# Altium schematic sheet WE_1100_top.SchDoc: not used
size A3; Date: not used; Author: not used; CompanyName: Würth Elektronik eiSos GmbH & Co. KG; Engineer: not used; Organization: not used; Address1: Max-Eyth-Str. 1; Address2: 74638 Waldenburg; Address3: not used; Address4: Germany; DocumentNumber: not used; Revision: not used
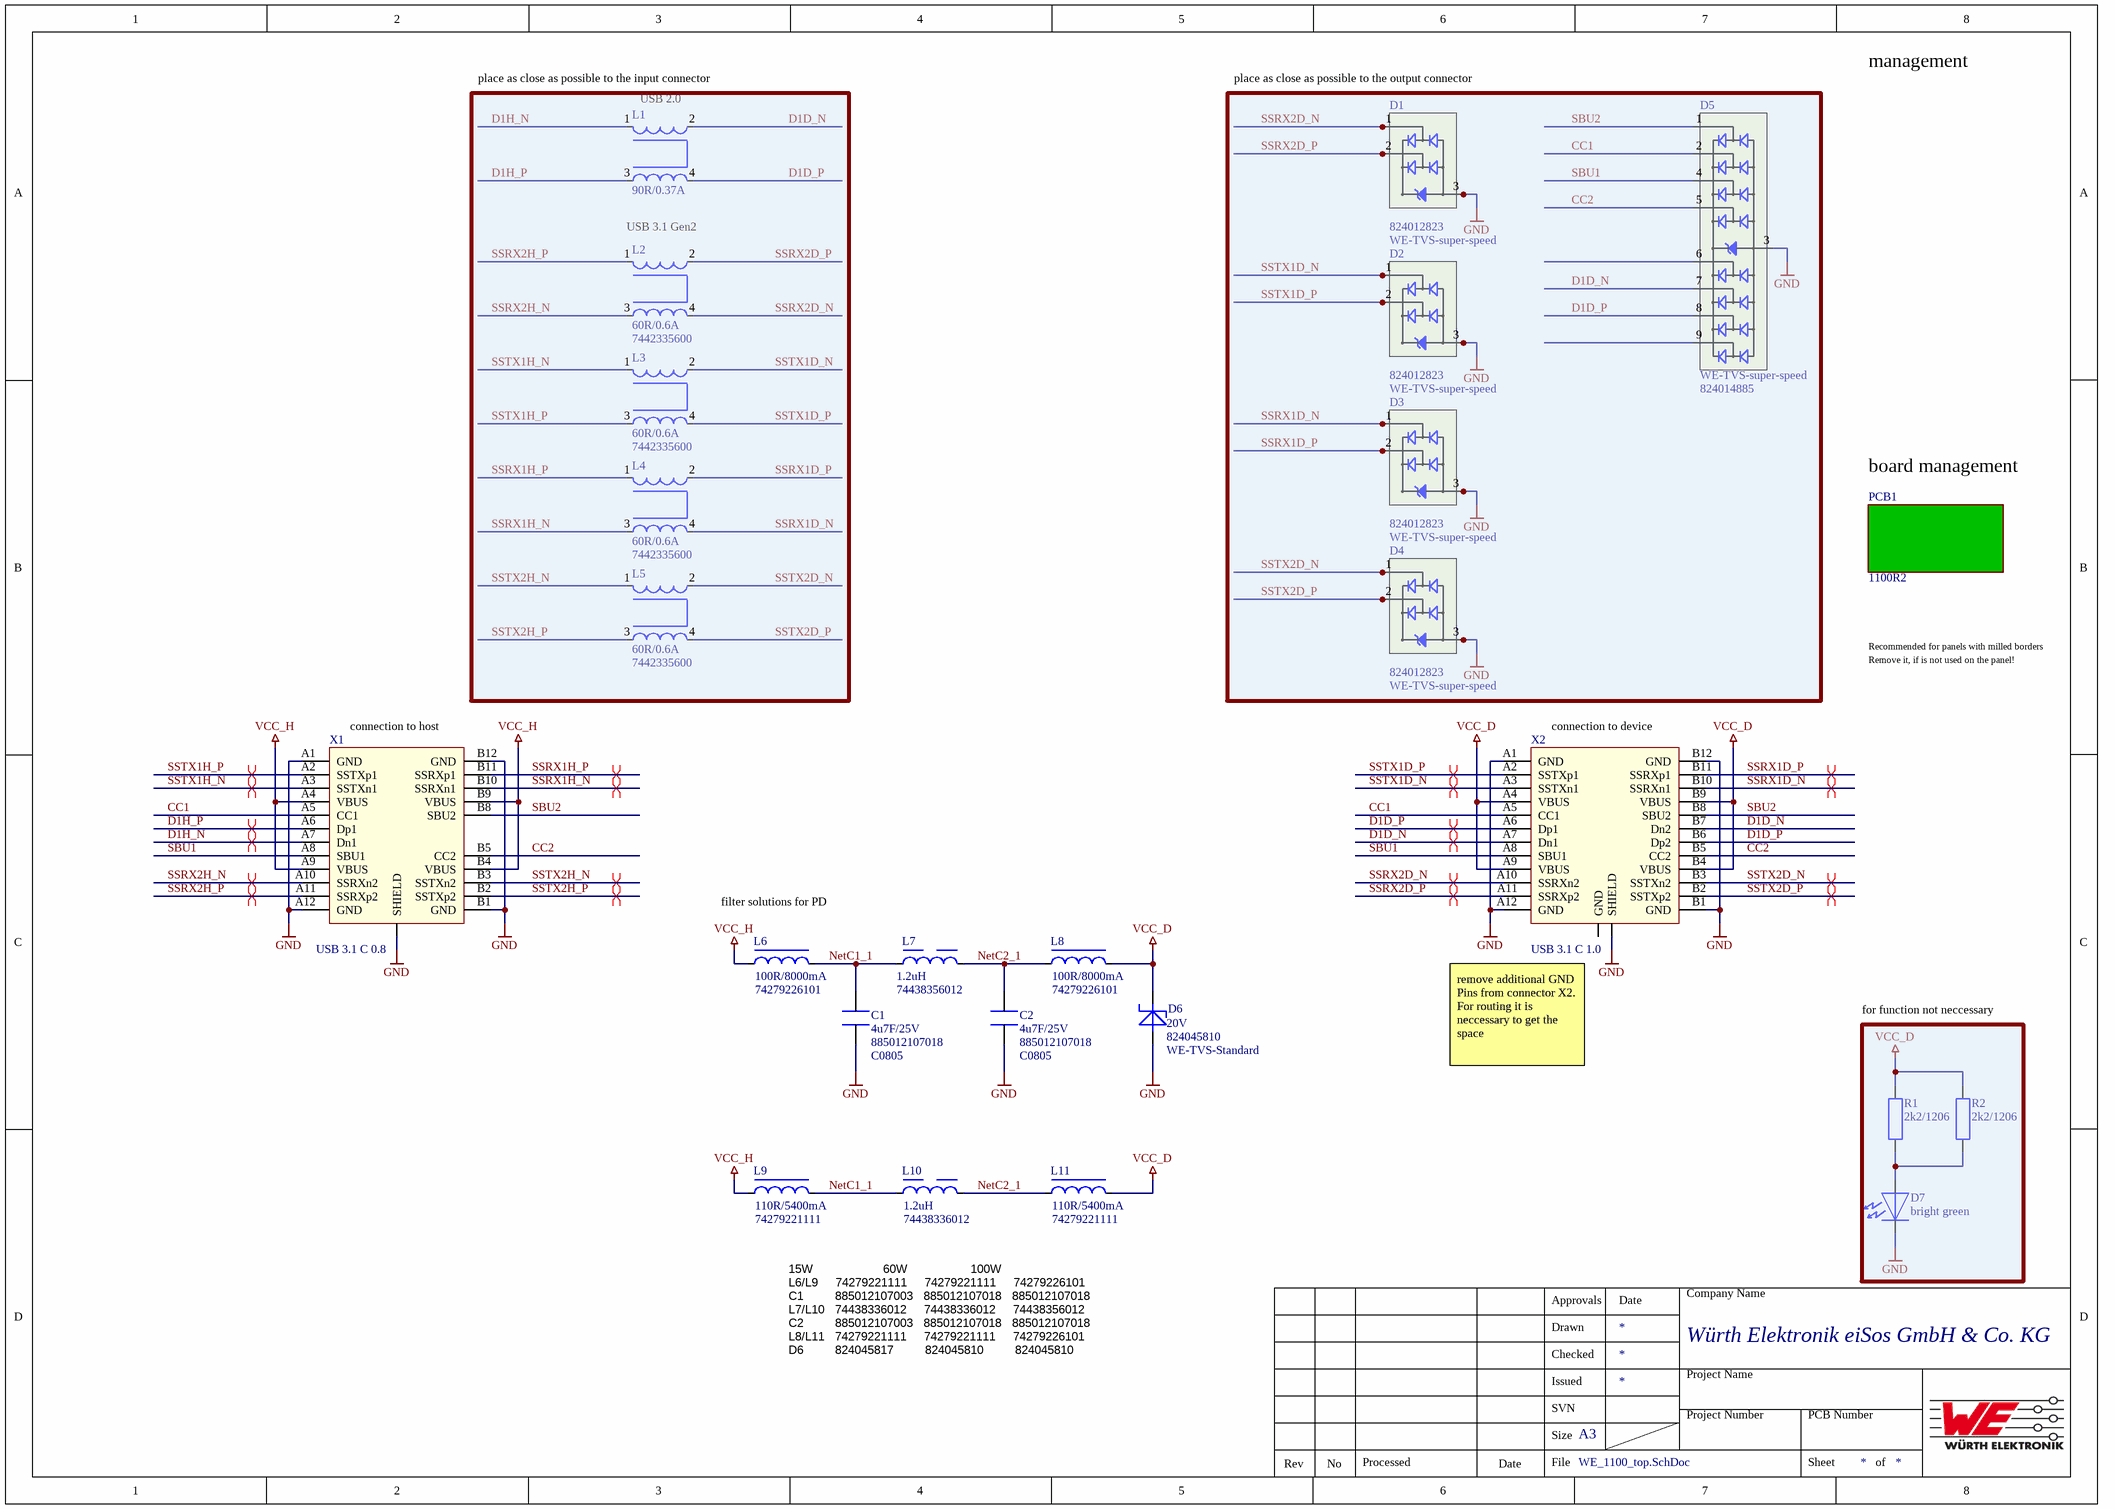
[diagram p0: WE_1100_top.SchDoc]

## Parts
C1  4u7F/25V  Art.-Code: 885012107018  Case: C0805  [C0805 (reflow)]
C2  4u7F/25V  Art.-Code: 885012107018  Case: C0805  [C0805 (reflow)]
D1  WE-TVS-super-speed  Part-No.: 824012823  [DFN88P100X50-6L]
D2  WE-TVS-super-speed  Part-No.: 824012823  [DFN88P100X50-6L]
D3  WE-TVS-super-speed  Part-No.: 824012823  [DFN88P100X50-6L]
D4  WE-TVS-super-speed  Part-No.: 824012823  [DFN88P100X50-6L]
D5  WE-TVS-super-speed  Part-No.: 824014885  [DFN90P380X55-9L]
D6  WE-TVS-Standard  Voltage: 20V  Part-No.: 824045810  [DFN110P160X55-2L]
D7  bright green  [LED-SMD-GR-2014X09L]
L1  90R/0.37A  [WE-CNSW-0805 (REFLOW)]
L2  60R/0.6A  Part-No.: 7442335600  [WE-CNSW-HF-0504 (REFLOW)]
L3  60R/0.6A  Part-No.: 7442335600  [WE-CNSW-HF-0504 (REFLOW)]
L4  60R/0.6A  Part-No.: 7442335600  [WE-CNSW-HF-0504 (REFLOW)]
L5  60R/0.6A  Part-No.: 7442335600  [WE-CNSW-HF-0504 (REFLOW)]
L6  100R/8000mA  Art.-Code: 74279226101  [WE-MPSB_1812]
L7  1.2uH  Art.-Code: 74438356012  [WE-MAPI_4020]
L8  100R/8000mA  Art.-Code: 74279226101  [WE-MPSB_1812]
L9  110R/5400mA  Art.-Code: 74279221111  [WE-MPSB_1206]
L10  1.2uH  Art.-Code: 74438336012  [WE-MAPI_3020]
L11  110R/5400mA  Art.-Code: 74279221111  [WE-MPSB_1206]
PCB1  1100R2  (mechanical)
R1  2k2/1206  [R1206 (reflow)]
R2  2k2/1206  [R1206 (reflow)]
X1  USB 3.1 C 0.8  [632712000011]
X2  USB 3.1 C 1.0  [632723100011]

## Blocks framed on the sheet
place as close as possible to the output connector: D1-D5
for function not neccessary: D7 R1 R2

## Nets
GND: C1.2 C2.2 D1.3(VDD) D1.4(VDD) D2.3(VDD) D2.4(VDD) D3.3(VDD) D3.4(VDD) D4.3(VDD) D4.4(VDD) D5.3(VDD) D6.2(I/O2) D7.1 X1.0(SHIELD) X1.A1(GND) X1.A12(GND) X1.B1(GND) X1.B12(GND) X2.0(SHIELD) X2.A1(GND) X2.A12(GND) X2.B1(GND) X2.B12(GND)
VCC_D: D6.1(I/O1) L8.2 L11.2 R1.2 R2.2 X2.A4(VBUS) X2.A9(VBUS) X2.B4(VBUS) X2.B9(VBUS)
VCC_H: L6.1 L9.1 X1.A4(VBUS) X1.A9(VBUS) X1.B4(VBUS) X1.B9(VBUS)
CC1: D5.2(I/O2) X1.A5(CC1) X2.A5(CC1)
CC2: D5.5(I/O4) X1.B5(CC2) X2.B5(CC2)
D1D_N: D5.7(NC) L1.2 X2.A7(Dn1) X2.B7(Dn2)
D1D_P: D5.8(GND) L1.4 X2.A6(Dp1) X2.B6(Dp2)
D1H_N: L1.1 X1.A7(Dn1)
D1H_P: L1.3 X1.A6(Dp1)
NetC1_1: C1.1 L6.2 L7.1 L9.2 L10.1
NetC2_1: C2.1 L7.2 L8.1 L10.2 L11.1
SBU1: D5.4(I/O3) X1.A8(SBU1) X2.A8(SBU1)
SBU2: D5.1(I/O1) X1.B8(SBU2) X2.B8(SBU2)
SSRX1D_N: D3.1(I/O1) D3.6(I/O1) L4.4 X2.B10(SSRXn1)
SSRX1D_P: D3.2(I/O2) D3.5(I/O2) L4.2 X2.B11(SSRXp1)
SSRX1H_N: L4.3 X1.B10(SSRXn1)
SSRX1H_P: L4.1 X1.B11(SSRXp1)
SSRX2D_N: D1.1(I/O1) D1.6(I/O1) L2.4 X2.A10(SSRXn2)
SSRX2D_P: D1.2(I/O2) D1.5(I/O2) L2.2 X2.A11(SSRXp2)
SSRX2H_N: L2.3 X1.A10(SSRXn2)
SSRX2H_P: L2.1 X1.A11(SSRXp2)
SSTX1D_N: D2.1(I/O1) D2.6(I/O1) L3.2 X2.A3(SSTXn1)
SSTX1D_P: D2.2(I/O2) D2.5(I/O2) L3.4 X2.A2(SSTXp1)
SSTX1H_N: L3.1 X1.A3(SSTXn1)
SSTX1H_P: L3.3 X1.A2(SSTXp1)
SSTX2D_N: D4.1(I/O1) D4.6(I/O1) L5.2 X2.B3(SSTXn2)
SSTX2D_P: D4.2(I/O2) D4.5(I/O2) L5.4 X2.B2(SSTXp2)
SSTX2H_N: L5.1 X1.B3(SSTXn2)
SSTX2H_P: L5.3 X1.B2(SSTXp2)
NetD7_2: D7.2 R1.1 R2.1

Not connected (* = marked no-connect by the designer): D5 6(NC) 9(NC); X2 GND

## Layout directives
differential pair: D1D_N, D1D_P, D1H_N, D1H_P, SSRX1D_N, SSRX1D_P, SSRX1H_N, SSRX1H_P, SSRX2D_N, SSRX2D_P, SSRX2H_N, SSRX2H_P, SSTX1D_N, SSTX1D_P, SSTX1H_N, SSTX1H_P, SSTX2D_N, SSTX2D_P, SSTX2H_N, SSTX2H_P

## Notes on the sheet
- (near L1) place as close as possible to the input connector
- (near L1) USB 2.0
- management
- USB 3.1 Gen2
- (near PCB1) board management
- Recommended for panels with milled borders
- Remove it, if is not used on the panel!
- (near X1) connection to host
- (near X2) connection to device
- filter solutions for PD
- (near X2) remove additional GND Pins from connector X2. For routing it is neccessary to get the space
- 15W                    60W                  100W
  L6/L9     74279221111     74279221111     74279226101
  C1         885012107003   885012107018   885012107018
  L7/L10   74438336012     74438336012     74438356012
  C2         885012107003   885012107018   885012107018
  L8/L11   74279221111     74279221111     74279226101
  D6         824045817         824045810         824045810

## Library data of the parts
C1 C2 = 4UF7/25-X5R-0805: Ceramic SMT X5R 4,7uF/25V 0805; Part-No.: X5R0805475M025DFCT10000; Manufacturer: WE; Value: 4.7u; Group: C-KERKO; Tolerance: 20%; TK: 15%; Voltage: 25V; Type: WCAP-CSGP; Obligation: no
D1-D4 = WE-TVS-ULC-DFN1012-6: TVS, diode, array, 2 channel ESD protection, 3.3V, DFN1012-6; Manufacturer: WE; Group: D-DIODE; Obligation: no; Type: TVS Diode
D5 = WE-TVS-ULC-DFN3810: TVS, diode, array, 8 channel ESD protection, 1.2V, DFN3810-9; Manufacturer: WE; Group: D-DIODE; Obligation: no; Type: TVS Diode
D6 = WE-TVS20-ULC-DFN1610: TVS, diode, unidir, ESD protection, 20V, DFN1610; Manufacturer: WE; Group: D-DIODE; Obligation: no; Type: TVS Diode
D7 = LED Chipled VS 0805: SMD-LED, Chipled 0805, brigth green; Manufacturer: WE; Part-No.: 150080VS75000; Group: O-LED; Current: 20mA; Voltage: 2.0V; Obligation: no
L1 = Z90R-370mA-WE-CNSW: Common mode line filter SMD WE-CNSW (USB, LVDS); Manufacturer: WE; Art.-Code: 744231091; Group: L-SPULE; Current: 370mA; Tolerance: 25%; Value: 90R; Voltage: 50VDC; Type: WE-CNSW 0805; Obligation: no
L2-L5 = Z60R-600mA-WE-CNSW HF: Common mode line filter SMD WE-CNSW HF (USB3.0); Manufacturer: WE; Group: L-SPULE; Current: 600mA; Tolerance: 25%; Value: 60R; Voltage: 20VDC; Type: WE-CNSW HF 0504; Obligation: no
L6 L8 = Z100R_8000mA_1812_MPSB: Multilayer Power Suppression Bead 1812 100R at 100MHz/0.006R; Manufacturer: WE; Group: L-FERRIT; Current: 8000mA; Tolerance: 25%; Voltage: 80VDC; Type: WE-MPSB; Obligation: no
L7 = 1UH2-5.8A-SMD-WE-MAPI 4020: Inductor SMT WE-MAPI 4020 1.2uH/5800mA; Manufacturer: WE; Current: 5.8A; Group: L-SPULE; Obligation: no; Tolerance: 20%; Value: 1u2; Voltage: 80VDC
L9 L11 = Z110R_5400mA_1206_MPSB: Multilayer Power Suppression Bead 1206 110R at 100MHz/0.0095R; Manufacturer: WE; Group: L-FERRIT; Current: 5400mA; Tolerance: 25%; Voltage: 80VDC; Type: WE-MPSB; Obligation: no
L10 = 1UH2-3.9A-SMD-WE-MAPI 3020: Inductor SMT WE-MAPI 3020 1.2uH/3900mA; Manufacturer: WE; Current: 3.9A; Group: L-SPULE; Obligation: no; Tolerance: 20%; Value: 1u2; Voltage: 80VDC
PCB1 = PCB: only for partlist; Art.-Code: NA; Obligation: no
R1 R2 = 2K2-1-1206: Resistor 2K2 1% 1206 E24; Manufacturer: Rohm; Part-No.: MCR18ERTF2201; Power: 1/4W; Value: 2.2k; Art.-Code: RHM2.20KCJTR-ND; Group: R-WIDERST; TK: 100ppm; Voltage: 200V; Obligation: no
X1 = ST-24 USB 3.1 C 0.8: male USB 3.1 Type C 24 pins 90° THT & SMT LP 0.8; Manufacturer: WE; Current: 5A; Group: X-STECKER; UL File: E323964; Voltage: 20V
X2 = BU-24 USB 3.1 C 1.0: female USB 3.1 Type C 24 pins 90° THT & SMT LP 1.0; Manufacturer: WE; Current: 5A; Group: X-BUCHSE; Obligation: no; UL File: E323964; Voltage: 20V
